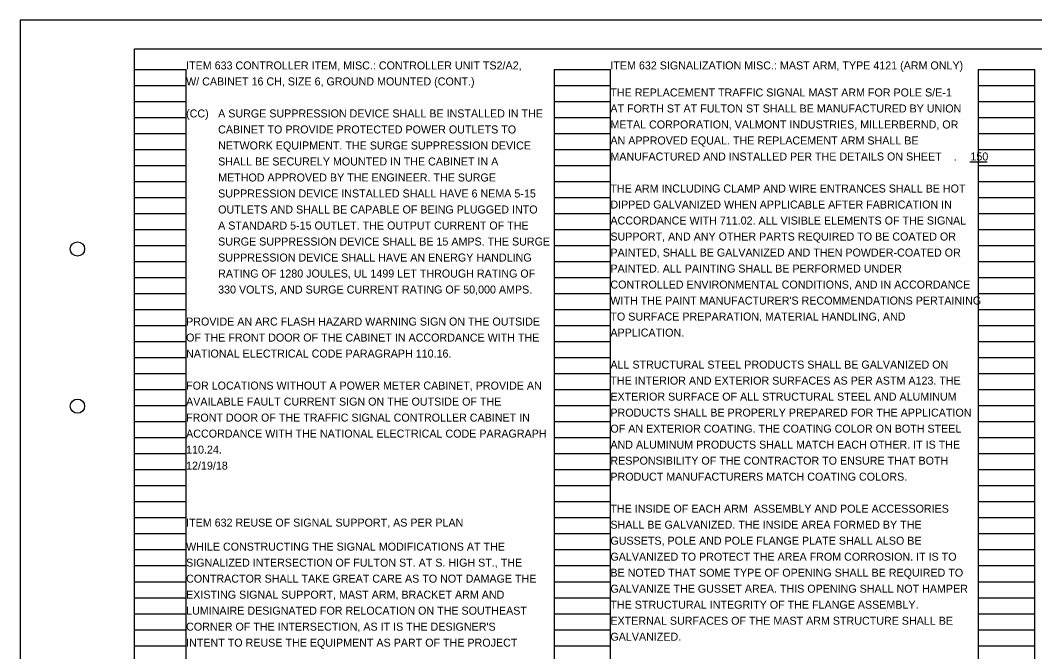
# Model space of a CAD drawing. Extents: x -15.1 to 53.7, y -46.4 to 36.
# Drawn here: x -0.51 to 17.23, y 3.45 to 14.49 of the extents above; entities that cross this region are included whole.
import ezdxf

# ---------------------------------------------------------------- set-up
doc = ezdxf.new("R2010")
doc.units = 0
for name, color, linetype in [('Default', 7, 'Continuous'), ('PF_P_Text', 7, 'Continuous'), ('SC_Scratch1', 7, 'Continuous'), ('SH_Cut_Line', 7, 'Continuous'), ('SH_Text', 7, 'Continuous')]:
    doc.layers.add(name, color=color, linetype=linetype)

msp = doc.modelspace()

# ---------------------------------------------------------------- linework, layer by layer
at = {"layer": 'Default'}
msp.add_line((16.403, 12.011), (16.097, 12.011), dxfattribs=at)
at = {"layer": 'PF_P_Text'}
msp.add_lwpolyline([(1.494, 13.992), (32.994, 13.992), (32.994, -7.008), (1.494, -7.008)], close=True, dxfattribs=at)
for centre in [(0.494, 10.492), (0.494, 7.742)]:
    msp.add_circle(centre, 0.125, dxfattribs=at)
at = {"layer": 'SC_Scratch1'}
for p, q in [((1.494, -6.528), (1.494, 13.632)), ((1.494, 13.632), (2.394, 13.632)), ((2.394, -6.528), (2.394, 13.632)), ((8.834, -6.528), (8.834, 13.632)), ((8.834, 13.632), (9.814, 13.632)), ((9.814, -6.528), (9.814, 13.632)), ((16.254, -6.528), (16.254, 13.632)), ((16.254, 13.632), (17.234, 13.632)), ((17.234, -6.528), (17.234, 13.632)), ((1.494, 13.352), (2.394, 13.352)), ((8.834, 13.352), (9.814, 13.352)), ((16.254, 13.352), (17.234, 13.352)), ((1.494, 13.072), (2.394, 13.072)), ((8.834, 13.072), (9.814, 13.072)), ((16.254, 13.072), (17.234, 13.072)), ((1.494, 12.792), (2.394, 12.792)), ((8.834, 12.792), (9.814, 12.792)), ((16.254, 12.792), (17.234, 12.792)), ((1.494, 12.512), (2.394, 12.512)), ((8.834, 12.512), (9.814, 12.512)), ((16.254, 12.512), (17.234, 12.512)), ((1.494, 12.232), (2.394, 12.232)), ((8.834, 12.232), (9.814, 12.232)), ((16.254, 12.232), (17.234, 12.232)), ((1.494, 11.952), (2.394, 11.952)), ((8.834, 11.952), (9.814, 11.952)), ((16.254, 11.952), (17.234, 11.952)), ((1.494, 11.672), (2.394, 11.672)), ((8.834, 11.672), (9.814, 11.672)), ((16.254, 11.672), (17.234, 11.672)), ((1.494, 11.392), (2.394, 11.392)), ((8.834, 11.392), (9.814, 11.392)), ((16.254, 11.392), (17.234, 11.392)), ((1.494, 11.112), (2.394, 11.112)), ((8.834, 11.112), (9.814, 11.112)), ((16.254, 11.112), (17.234, 11.112)), ((1.494, 10.832), (2.394, 10.832)), ((8.834, 10.832), (9.814, 10.832)), ((16.254, 10.832), (17.234, 10.832)), ((1.494, 10.552), (2.394, 10.552)), ((8.834, 10.552), (9.814, 10.552)), ((16.254, 10.552), (17.234, 10.552)), ((1.494, 10.272), (2.394, 10.272)), ((8.834, 10.272), (9.814, 10.272)), ((16.254, 10.272), (17.234, 10.272)), ((1.494, 9.992), (2.394, 9.992)), ((8.834, 9.992), (9.814, 9.992)), ((16.254, 9.992), (17.234, 9.992)), ((1.494, 9.712), (2.394, 9.712)), ((8.834, 9.712), (9.814, 9.712)), ((16.254, 9.712), (17.234, 9.712)), ((1.494, 9.432), (2.394, 9.432)), ((8.834, 9.432), (9.814, 9.432)), ((16.254, 9.432), (17.234, 9.432)), ((1.494, 9.152), (2.394, 9.152)), ((8.834, 9.152), (9.814, 9.152)), ((16.254, 9.152), (17.234, 9.152)), ((1.494, 8.872), (2.394, 8.872)), ((8.834, 8.872), (9.814, 8.872)), ((16.254, 8.872), (17.234, 8.872)), ((1.494, 8.592), (2.394, 8.592)), ((8.834, 8.592), (9.814, 8.592)), ((16.254, 8.592), (17.234, 8.592)), ((1.494, 8.312), (2.394, 8.312)), ((8.834, 8.312), (9.814, 8.312)), ((16.254, 8.312), (17.234, 8.312)), ((1.494, 8.032), (2.394, 8.032)), ((8.834, 8.032), (9.814, 8.032)), ((16.254, 8.032), (17.234, 8.032)), ((1.494, 7.752), (2.394, 7.752)), ((8.834, 7.752), (9.814, 7.752)), ((16.254, 7.752), (17.234, 7.752)), ((1.494, 7.472), (2.394, 7.472)), ((8.834, 7.472), (9.814, 7.472)), ((16.254, 7.472), (17.234, 7.472)), ((1.494, 7.192), (2.394, 7.192)), ((8.834, 7.192), (9.814, 7.192)), ((16.254, 7.192), (17.234, 7.192)), ((1.494, 6.912), (2.394, 6.912)), ((8.834, 6.912), (9.814, 6.912)), ((16.254, 6.912), (17.234, 6.912)), ((1.494, 6.632), (2.394, 6.632)), ((8.834, 6.632), (9.814, 6.632)), ((16.254, 6.632), (17.234, 6.632)), ((1.494, 6.352), (2.394, 6.352)), ((8.834, 6.352), (9.814, 6.352)), ((16.254, 6.352), (17.234, 6.352)), ((1.494, 6.072), (2.394, 6.072)), ((8.834, 6.072), (9.814, 6.072)), ((16.254, 6.072), (17.234, 6.072)), ((1.494, 5.792), (2.394, 5.792)), ((8.834, 5.792), (9.814, 5.792)), ((16.254, 5.792), (17.234, 5.792)), ((1.494, 5.512), (2.394, 5.512)), ((8.834, 5.512), (9.814, 5.512)), ((16.254, 5.512), (17.234, 5.512)), ((1.494, 5.232), (2.394, 5.232)), ((8.834, 5.232), (9.814, 5.232)), ((16.254, 5.232), (17.234, 5.232)), ((1.494, 4.952), (2.394, 4.952)), ((8.834, 4.952), (9.814, 4.952)), ((16.254, 4.952), (17.234, 4.952)), ((1.494, 4.672), (2.394, 4.672)), ((8.834, 4.672), (9.814, 4.672)), ((16.254, 4.672), (17.234, 4.672)), ((1.494, 4.392), (2.394, 4.392)), ((8.834, 4.392), (9.814, 4.392)), ((16.254, 4.392), (17.234, 4.392)), ((1.494, 4.112), (2.394, 4.112)), ((8.834, 4.112), (9.814, 4.112)), ((16.254, 4.112), (17.234, 4.112)), ((1.494, 3.832), (2.394, 3.832)), ((8.834, 3.832), (9.814, 3.832)), ((16.254, 3.832), (17.234, 3.832)), ((1.494, 3.552), (2.394, 3.552)), ((8.834, 3.552), (9.814, 3.552)), ((16.254, 3.552), (17.234, 3.552))]:
    msp.add_line(p, q, dxfattribs=at)
at = {"layer": 'SH_Cut_Line'}
msp.add_lwpolyline([(-0.506, -7.508), (33.494, -7.508), (33.494, 14.492), (-0.506, 14.492)], close=True, dxfattribs=at)

# ---------------------------------------------------------------- texts
at = {"layer": 'SH_Text'}
for s, p in [('ITEM 633 CONTROLLER ITEM, MISC.: CONTROLLER UNIT TS2/A2, ', (2.394, 13.632)), ('ITEM 632 SIGNALIZATION MISC.: MAST ARM, TYPE 4121 (ARM ONLY)', (9.814, 13.632)), ('W/ CABINET 16 CH, SIZE 6, GROUND MOUNTED (CONT.)', (2.394, 13.352)), ('(CC)', (2.394, 12.792)), ('A SURGE SUPPRESSION DEVICE SHALL BE INSTALLED IN THE ', (2.954, 12.792)), ('CABINET TO PROVIDE PROTECTED POWER OUTLETS TO ', (2.954, 12.512)), ('NETWORK EQUIPMENT. THE SURGE SUPPRESSION DEVICE ', (2.954, 12.232)), ('SHALL BE SECURELY MOUNTED IN THE CABINET IN A ', (2.954, 11.952)), ('METHOD APPROVED BY THE ENGINEER. THE SURGE ', (2.954, 11.672)), ('SUPPRESSION DEVICE INSTALLED SHALL HAVE 6 NEMA 5-15 ', (2.954, 11.392)), ('OUTLETS AND SHALL BE CAPABLE OF BEING PLUGGED INTO ', (2.954, 11.112)), ('A STANDARD 5-15 OUTLET. THE OUTPUT CURRENT OF THE ', (2.954, 10.832)), ('SURGE SUPPRESSION DEVICE SHALL BE 15 AMPS. THE SURGE ', (2.954, 10.552)), ('SUPPRESSION DEVICE SHALL HAVE AN ENERGY HANDLING ', (2.954, 10.272)), ('RATING OF 1280 JOULES, UL 1499 LET THROUGH RATING OF ', (2.954, 9.992)), ('330 VOLTS, AND SURGE CURRENT RATING OF 50,000 AMPS.', (2.954, 9.712)), ('PROVIDE AN ARC FLASH HAZARD WARNING SIGN ON THE OUTSIDE ', (2.394, 9.152)), ('OF THE FRONT DOOR OF THE CABINET IN ACCORDANCE WITH THE ', (2.394, 8.872)), ('NATIONAL ELECTRICAL CODE PARAGRAPH 110.16.', (2.394, 8.592)), ('FOR LOCATIONS WITHOUT A POWER METER CABINET, PROVIDE AN ', (2.394, 8.032)), ('AVAILABLE FAULT CURRENT SIGN ON THE OUTSIDE OF THE ', (2.394, 7.752)), ('FRONT DOOR OF THE TRAFFIC SIGNAL CONTROLLER CABINET IN ', (2.394, 7.472)), ('ACCORDANCE WITH THE NATIONAL ELECTRICAL CODE PARAGRAPH ', (2.394, 7.192)), ('110.24.', (2.394, 6.912)), ('12/19/18', (2.394, 6.632)), ('ITEM 632 REUSE OF SIGNAL SUPPORT, AS PER PLAN', (2.394, 5.635))]:
    msp.add_text(s, height=0.14, rotation=0, dxfattribs=at).set_placement(p)
for s, p in [('THE REPLACEMENT TRAFFIC SIGNAL MAST ARM FOR POLE S/E-1 ', (9.814, 13.159)), ('AT FORTH ST AT FULTON ST SHALL BE MANUFACTURED BY UNION ', (9.814, 12.879)), ('METAL CORPORATION, VALMONT INDUSTRIES, MILLERBERND, OR ', (9.814, 12.599)), ('AN APPROVED EQUAL. THE REPLACEMENT ARM SHALL BE ', (9.814, 12.319)), ('MANUFACTURED AND INSTALLED PER THE DETAILS ON SHEET    . ', (9.814, 12.039)), ('150', (16.11, 12.04)), ('THE ARM INCLUDING CLAMP AND WIRE ENTRANCES SHALL BE HOT ', (9.814, 11.479)), ('DIPPED GALVANIZED WHEN APPLICABLE AFTER FABRICATION IN ', (9.814, 11.199)), ('ACCORDANCE WITH 711.02. ALL VISIBLE ELEMENTS OF THE SIGNAL ', (9.814, 10.919)), ('SUPPORT, AND ANY OTHER PARTS REQUIRED TO BE COATED OR ', (9.814, 10.639)), ('PAINTED, SHALL BE GALVANIZED AND THEN POWDER-COATED OR ', (9.814, 10.359)), ('PAINTED. ALL PAINTING SHALL BE PERFORMED UNDER ', (9.814, 10.079)), ('CONTROLLED ENVIRONMENTAL CONDITIONS, AND IN ACCORDANCE ', (9.814, 9.799)), ("WITH THE PAINT MANUFACTURER'S RECOMMENDATIONS PERTAINING ", (9.814, 9.519)), ('TO SURFACE PREPARATION, MATERIAL HANDLING, AND ', (9.814, 9.239)), ('APPLICATION.', (9.814, 8.959)), ('ALL STRUCTURAL STEEL PRODUCTS SHALL BE GALVANIZED ON ', (9.814, 8.399)), ('THE INTERIOR AND EXTERIOR SURFACES AS PER ASTM A123. THE ', (9.814, 8.119)), ('EXTERIOR SURFACE OF ALL STRUCTURAL STEEL AND ALUMINUM ', (9.814, 7.839)), ('PRODUCTS SHALL BE PROPERLY PREPARED FOR THE APPLICATION ', (9.814, 7.559)), ('OF AN EXTERIOR COATING. THE COATING COLOR ON BOTH STEEL ', (9.814, 7.279)), ('AND ALUMINUM PRODUCTS SHALL MATCH EACH OTHER. IT IS THE ', (9.814, 6.999)), ('RESPONSIBILITY OF THE CONTRACTOR TO ENSURE THAT BOTH ', (9.814, 6.719)), ('PRODUCT MANUFACTURERS MATCH COATING COLORS.', (9.814, 6.439)), ('THE INSIDE OF EACH ARM  ASSEMBLY AND POLE ACCESSORIES ', (9.814, 5.879)), ('SHALL BE GALVANIZED. THE INSIDE AREA FORMED BY THE ', (9.814, 5.599)), ('WHILE CONSTRUCTING THE SIGNAL MODIFICATIONS AT THE ', (2.394, 5.215)), ('GUSSETS, POLE AND POLE FLANGE PLATE SHALL ALSO BE ', (9.814, 5.319)), ('GALVANIZED TO PROTECT THE AREA FROM CORROSION. IT IS TO ', (9.814, 5.039)), ('SIGNALIZED INTERSECTION OF FULTON ST. AT S. HIGH ST., THE ', (2.394, 4.935)), ('CONTRACTOR SHALL TAKE GREAT CARE AS TO NOT DAMAGE THE ', (2.394, 4.655)), ('BE NOTED THAT SOME TYPE OF OPENING SHALL BE REQUIRED TO ', (9.814, 4.759)), ('GALVANIZE THE GUSSET AREA. THIS OPENING SHALL NOT HAMPER ', (9.814, 4.479)), ('EXISTING SIGNAL SUPPORT, MAST ARM, BRACKET ARM AND ', (2.394, 4.375)), ('THE STRUCTURAL INTEGRITY OF THE FLANGE ASSEMBLY. ', (9.814, 4.199)), ('LUMINAIRE DESIGNATED FOR RELOCATION ON THE SOUTHEAST ', (2.394, 4.095)), ("CORNER OF THE INTERSECTION, AS IT IS THE DESIGNER'S ", (2.394, 3.815)), ('EXTERNAL SURFACES OF THE MAST ARM STRUCTURE SHALL BE ', (9.814, 3.919)), ('GALVANIZED.', (9.814, 3.639)), ('INTENT TO REUSE THE EQUIPMENT AS PART OF THE PROJECT ', (2.394, 3.535))]:
    msp.add_text(s, height=0.14, dxfattribs=at).set_placement(p)

doc.saveas('drawing.dxf')
